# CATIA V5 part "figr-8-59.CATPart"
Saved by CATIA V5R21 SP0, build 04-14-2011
Part number: Part1
Bounding box of the stored display mesh (mm): x -50.499 to 50.499, y -68.48 to 68.48, z -50 to 50
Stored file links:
  D:\CATIA V5R21 E-RESOURCES\CATIA-V5R21\catia-v5r21-prt\c08-catia-v5r20-prt\c08-catia-v5r21-figr-8-59.CATPart
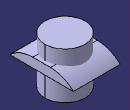
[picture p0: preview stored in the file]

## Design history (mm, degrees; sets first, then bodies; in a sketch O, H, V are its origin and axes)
Body1 (main body)
  Sketch1 on xy-plane, origin (0, 0, 0), H (1, 0, 0), V (0, 1, 0)
    line L1 (-50.499, 68.4797) -> (50.499, 68.4797)
    line L2 (50.499, 68.4797) -> (50.499, -68.4797)
    line L3 (50.499, -68.4797) -> (-50.499, -68.4797)
    line L4 (-50.499, -68.4797) -> (-50.499, 68.4797)
    axis line L5 (50.499, -68.4797) -> (-50.499, 68.4797)
    horizontal: L1 H, L3 H
    vertical: L2 V, L4 V
    midpoint: O L5
  Pad1: profile Sketch1, direction (0, 0, 1), length 20
  Fillet1: radius 71, on edge [face of Pad1 | face of Pad1]
  Fillet2: radius 71, on edge [face of Pad1 | face of Pad1]
Body2
  Sketch2 on xy-plane, origin (0, 0, 0), H (1, 0, 0), V (0, 1, 0)
    circle A1 centre (0, 0) radius 43.2524
    point P1 (0, 43.2524)
    coincidence: A1 P1, P1 V
  Pocket1: profile Sketch2, direction (0, 0, -1), length 50, mirrored extent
